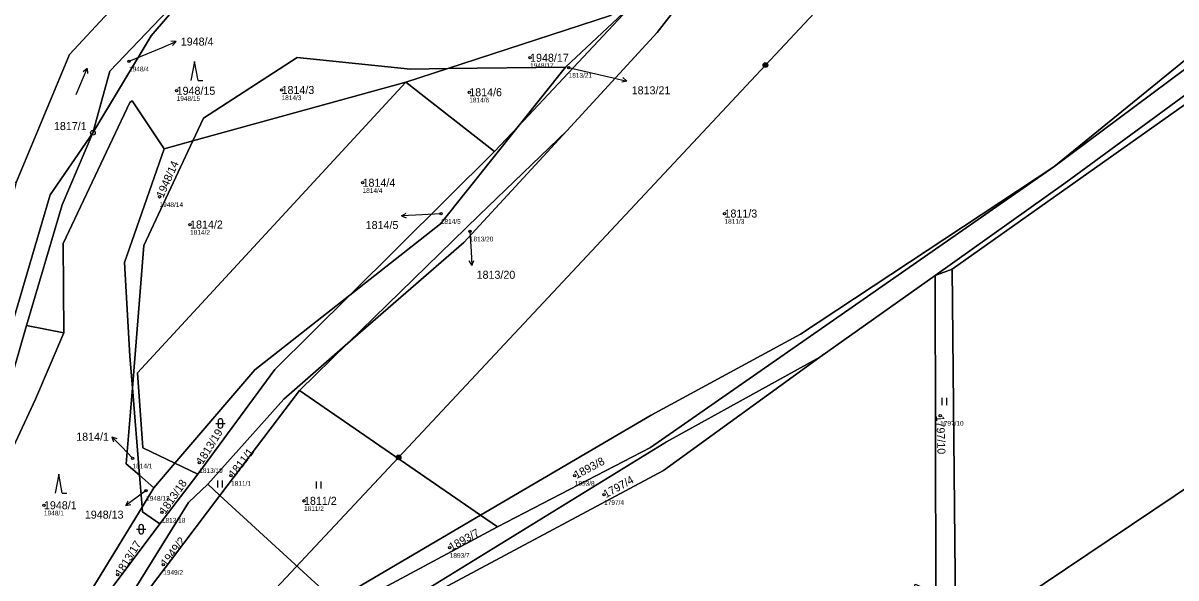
# Model space of a CAD drawing. Extents: x -762274 to -759271, y -1061928 to -1059060.
# Drawn here: x -761266.1 to -761021.1, y -1060846.7 to -1060728.9 of the extents above; entities that cross this region are included whole.
import ezdxf

# ---------------------------------------------------------------- set-up
doc = ezdxf.new("R2010")
doc.units = 0
for name, color, linetype in [('Definiční body', 7, 'Continuous'), ('Hranice parcel', 7, 'Continuous'), ('Parcelní čísla', 7, 'Continuous'), ('Polygon parcely', 7, 'Continuous'), ('Pop  PČ popisy', 7, 'Continuous'), ('Poz předměty', 7, 'Continuous'), ('Značky bodu BP', 7, 'Continuous'), ('Značky kultur', 7, 'Continuous')]:
    doc.layers.add(name, color=color, linetype=linetype)

msp = doc.modelspace()

# ---------------------------------------------------------------- linework, layer by layer
at = {"layer": 'Definiční body'}
for centre in [(-761243.55, -1060737), (-761158.36, -1060736.26), (-761150.17, -1060738.33), (-761233.45, -1060743.27), (-761211.16, -1060743.1), (-761171.28, -1060743.58), (-761193.95, -1060762.8), (-761237.08, -1060765.79), (-761177.31, -1060769.37), (-761117.05, -1060769.34), (-761230.59, -1060771.67), (-761171.15, -1060773.09), (-761071.23, -1060812.24), (-761242.82, -1060821.3), (-761228.64, -1060822.27), (-761221.88, -1060824.99), (-761148.87, -1060824.98), (-761239.93, -1060828.18), (-761142.63, -1060829.05), (-761261.64, -1060831.29), (-761206.39, -1060830.35), (-761236.58, -1060832.82), (-761175.43, -1060840.28), (-761236.3, -1060843.9), (-761245.95, -1060846.02)]:
    msp.add_circle(centre, 0.25, dxfattribs=at)
at = {"layer": 'Hranice parcel'}
for p, q in [((-761136.35, -1060724.75), (-761160.9, -1060750.86)), ((-761136.35, -1060724.75), (-761150.83, -1060738.27)), ((-761175.85, -1060738.56), (-761141.29, -1060727.28)), ((-761150.83, -1060738.27), (-761175.85, -1060738.56)), ((-761150.83, -1060738.27), (-761160.9, -1060750.86)), ((-761184.74, -1060741.46), (-761175.85, -1060738.56)), ((-761184.74, -1060741.46), (-761229.98, -1060753.9)), ((-761165.91, -1060756.19), (-761184.74, -1060741.46)), ((-761160.9, -1060750.86), (-761165.91, -1060756.19)), ((-761229.98, -1060753.9), (-761236.08, -1060755.58)), ((-761196.66, -1060786.66), (-761165.91, -1060756.19)), ((-761068.71, -1060781.12), (-761072.32, -1060782.49)), ((-761067.91, -1060860.48), (-761068.71, -1060781.12)), ((-761072.32, -1060782.49), (-761096.77, -1060799.85)), ((-761072.15, -1060849.9), (-761072.32, -1060782.49)), ((-761257.42, -1060794.67), (-761265.37, -1060793.08)), ((-761207.35, -1060806.93), (-761197.07, -1060796.9)), ((-761241.35, -1060824.93), (-761242.86, -1060806.32)), ((-761224.24, -1060829.21), (-761207.35, -1060806.93)), ((-761168.87, -1060833.39), (-761207.35, -1060806.93)), ((-761233.8, -1060822.36), (-761238.26, -1060827.57)), ((-761228.92, -1060824.71), (-761233.8, -1060822.36)), ((-761241.35, -1060824.93), (-761238.26, -1060827.57)), ((-761240.8, -1060831.72), (-761241.35, -1060824.93)), ((-761228.92, -1060824.71), (-761237.04, -1060835.2)), ((-761238.26, -1060827.57), (-761240.8, -1060831.72)), ((-761226.82, -1060826.84), (-761224.24, -1060829.21)), ((-761224.24, -1060829.21), (-761199.86, -1060851.57)), ((-761269.22, -1060878.2), (-761240.8, -1060831.72)), ((-761199.86, -1060851.57), (-761168.87, -1060833.39)), ((-761165.27, -1060835.87), (-761168.87, -1060833.39)), ((-761237.04, -1060835.2), (-761269.22, -1060878.2))]:
    msp.add_line(p, q, dxfattribs=at)
for points in [[(-761150.58, -1060751.74), (-761131.38, -1060730.87), (-761089.23, -1060676.77)], [(-760956.23, -1060685.96), (-760987.34, -1060716.59), (-761010.54, -1060737.84), (-761044.51, -1060762.75), (-761072.32, -1060782.49)], [(-761217.1, -1060693.41), (-761256.19, -1060735.55), (-761267.53, -1060762.74)], [(-761047.09, -1060759.39), (-761014.77, -1060733.14), (-760991.21, -1060712.56), (-760986.53, -1060707.75)], [(-760985.12, -1060709.16), (-761001.82, -1060725.75), (-761047.09, -1060759.39)], [(-761251.25, -1060752.17), (-761238.85, -1060731.63), (-761224.56, -1060714.9)], [(-761251.25, -1060752.17), (-761247.66, -1060739.1), (-761224.56, -1060714.9)], [(-760998.26, -1060731.71), (-761019.31, -1060746.24), (-761068.71, -1060781.12)], [(-761175.85, -1060738.56), (-761183.77, -1060738.65), (-761207.85, -1060736.23), (-761227.73, -1060749.1), (-761229.98, -1060753.9)], [(-761233.8, -1060822.36), (-761240.63, -1060819.07), (-761241.79, -1060803.18), (-761184.74, -1060741.46)], [(-761236.08, -1060755.58), (-761242.87, -1060745.4), (-761243.41, -1060745.74), (-761257.57, -1060775.67), (-761257.42, -1060794.67)], [(-761322.34, -1060894.54), (-761306.2, -1060874.72), (-761295.06, -1060858.65), (-761282.76, -1060836.42), (-761271.84, -1060804.34), (-761260.29, -1060765.39), (-761251.25, -1060752.17)], [(-761265.37, -1060793.08), (-761257.78, -1060767.49), (-761251.25, -1060752.17)], [(-761150.58, -1060751.74), (-761172.46, -1060775.52), (-761197.07, -1060796.9)], [(-761197.07, -1060796.9), (-761169.2, -1060769.68), (-761150.58, -1060751.74)], [(-761160.9, -1060750.86), (-761177.42, -1060771.52), (-761196.66, -1060786.66)], [(-761229.98, -1060753.9), (-761240.39, -1060776.11), (-761242.86, -1060806.32)], [(-761242.86, -1060806.32), (-761243.4, -1060799.63), (-761244.52, -1060779.75), (-761236.08, -1060755.58)], [(-761168.87, -1060833.39), (-761132.66, -1060812.15), (-761100.92, -1060794.93), (-761047.09, -1060759.39)], [(-761047.09, -1060759.39), (-761132.79, -1060819.05), (-761165.27, -1060835.87)], [(-760940.46, -1060777.01), (-760979.27, -1060801), (-761067.91, -1060860.48)], [(-761196.66, -1060786.66), (-761216.82, -1060802.53), (-761233.8, -1060822.36)], [(-761196.66, -1060786.66), (-761212.59, -1060802.45), (-761228.92, -1060824.71)], [(-761257.42, -1060794.67), (-761263.46, -1060808.77), (-761271.01, -1060824.88), (-761282.26, -1060861.39), (-761309.99, -1060889.4), (-761332.25, -1060918.32), (-761344.99, -1060927.62), (-761357.23, -1060933.34)], [(-761322.34, -1060894.54), (-761311.63, -1060884.88), (-761291.98, -1060860.89), (-761277.62, -1060835.42), (-761265.37, -1060793.08)], [(-761226.82, -1060826.84), (-761210.7, -1060808.73), (-761197.07, -1060796.9)], [(-761096.77, -1060799.85), (-761129.39, -1060817.83), (-761194.75, -1060858.03), (-761196.4, -1060859.25)], [(-761176.9, -1060848.97), (-761130.01, -1060823.92), (-761096.77, -1060799.85)], [(-761241.35, -1060824.93), (-761244.18, -1060822.51), (-761242.86, -1060806.32)], [(-761255.81, -1060870.74), (-761230.94, -1060830.68), (-761226.82, -1060826.84)], [(-761224.24, -1060829.21), (-761234.57, -1060842.83), (-761255.81, -1060870.74)], [(-761237.04, -1060835.2), (-761240.72, -1060832.67), (-761240.8, -1060831.72)], [(-761165.27, -1060835.87), (-761205.15, -1060857.25), (-761212.81, -1060861.91)]]:
    msp.add_lwpolyline(points, dxfattribs=at)
at = {"layer": 'Polygon parcely'}
for points in [[(-760986.1, -1060427.01), (-761021.62, -1060461.75), (-761022.5, -1060462.61), (-761040.97, -1060481.7), (-761053.88, -1060494.01), (-761069.92, -1060510.73), (-761079.43, -1060561.33), (-761089.56, -1060581.89), (-761099.86, -1060588.03), (-761128.14, -1060604.64), (-761140.02, -1060611.62), (-761149.18, -1060620.52), (-761153.48, -1060624.27), (-761155.89, -1060626.89), (-761214.07, -1060690.14), (-761217.1, -1060693.41), (-761256.19, -1060735.55), (-761267.53, -1060762.74), (-761275.36, -1060791.23), (-761278.82, -1060803.8), (-761288.4, -1060833.69), (-761301.74, -1060855.91), (-761311.33, -1060870.36), (-761329.82, -1060890.35)], [(-761271.84, -1060804.34), (-761260.29, -1060765.39), (-761251.25, -1060752.17), (-761247.66, -1060739.1), (-761224.56, -1060714.9), (-761213.5, -1060703.49), (-761207.85, -1060697.66), (-761147.16, -1060632.45), (-761145.06, -1060630.19), (-761131.3, -1060618.58), (-761095.24, -1060593.07), (-761084.28, -1060581.28), (-761075.53, -1060563.54), (-761068.42, -1060523.86), (-761062.44, -1060514.01), (-761052.71, -1060501.89), (-761037.42, -1060487.37), (-761035.26, -1060484.89), (-761025.32, -1060476.46), (-761017.38, -1060469.64)], [(-761269.22, -1060878.2), (-761240.8, -1060831.72), (-761241.35, -1060824.93), (-761244.18, -1060822.51), (-761242.86, -1060806.32), (-761243.4, -1060799.63), (-761244.52, -1060779.75), (-761236.08, -1060755.58), (-761242.87, -1060745.4), (-761243.41, -1060745.74), (-761257.57, -1060775.67), (-761257.42, -1060794.67), (-761263.46, -1060808.77), (-761271.01, -1060824.88)]]:
    msp.add_lwpolyline(points, dxfattribs=at)
for points in [[(-761010.54, -1060737.84), (-761044.51, -1060762.75), (-761072.32, -1060782.49), (-761068.71, -1060781.12), (-761019.31, -1060746.24), (-760998.26, -1060731.71), (-760977.63, -1060710.74), (-760951.25, -1060688.71), (-760936.2, -1060676.76), (-760933.83, -1060674.97), (-760921.43, -1060661.84), (-760891.41, -1060629.81), (-760884.45, -1060617.18), (-760890.91, -1060624.68), (-760920.97, -1060652.28), (-760926.73, -1060658.56), (-760939.63, -1060672.64), (-760956.23, -1060685.96), (-760987.34, -1060716.59)], [(-761261.47, -1060634.17), (-761268.62, -1060626.09), (-761333.35, -1060711.53), (-761364.51, -1060749.36), (-761306.96, -1060796.48), (-761300.33, -1060786.52), (-761290.49, -1060780.8), (-761275.58, -1060760.1), (-761267.53, -1060762.74), (-761256.19, -1060735.55), (-761217.1, -1060693.41), (-761221.44, -1060691.82), (-761240.65, -1060679.96), (-761229.58, -1060659.37), (-761237.29, -1060653.65), (-761241.79, -1060652.49)], [(-761089.23, -1060676.77), (-761131.38, -1060730.87), (-761150.58, -1060751.74), (-761172.46, -1060775.52), (-761197.07, -1060796.9), (-761207.35, -1060806.93), (-761168.87, -1060833.39), (-761132.66, -1060812.15), (-761100.92, -1060794.93), (-761047.09, -1060759.39), (-761014.77, -1060733.14), (-760991.21, -1060712.56), (-760986.53, -1060707.75), (-761055.77, -1060638.88)], [(-761141.29, -1060727.28), (-761143.4, -1060662), (-761146.9, -1060677.31), (-761151.84, -1060691.43), (-761165.92, -1060714.26), (-761176, -1060722.65), (-761193.74, -1060720.96), (-761198.85, -1060715.54), (-761224.56, -1060714.9), (-761238.85, -1060731.63), (-761251.25, -1060752.17), (-761257.78, -1060767.49), (-761265.37, -1060793.08), (-761257.42, -1060794.67), (-761257.57, -1060775.67), (-761243.41, -1060745.74), (-761242.87, -1060745.4), (-761236.08, -1060755.58), (-761229.98, -1060753.9), (-761227.73, -1060749.1), (-761207.85, -1060736.23), (-761183.77, -1060738.65), (-761175.85, -1060738.56)], [(-761136.35, -1060724.75), (-761160.9, -1060750.86), (-761177.42, -1060771.52), (-761196.66, -1060786.66), (-761212.59, -1060802.45), (-761228.92, -1060824.71), (-761237.04, -1060835.2), (-761269.22, -1060878.2), (-761298.8, -1060926.56), (-761348.67, -1060986.94), (-761354.62, -1061001.46), (-761299.71, -1060929.29), (-761269.45, -1060888.66), (-761255.81, -1060870.74), (-761230.94, -1060830.68), (-761226.82, -1060826.84), (-761210.7, -1060808.73), (-761197.07, -1060796.9), (-761169.2, -1060769.68), (-761150.58, -1060751.74), (-761131.38, -1060730.87), (-761089.23, -1060676.77), (-761095.67, -1060673.39)], [(-761132.79, -1060819.05), (-761165.27, -1060835.87), (-761205.15, -1060857.25), (-761212.81, -1060861.91), (-761211.5, -1060867.36), (-761207.78, -1060865.29), (-761204.41, -1060863.47), (-761196.4, -1060859.25), (-761194.75, -1060858.03), (-761129.39, -1060817.83), (-761096.77, -1060799.85), (-761072.32, -1060782.49), (-761044.51, -1060762.75), (-761010.54, -1060737.84), (-760987.34, -1060716.59), (-760956.23, -1060685.96), (-760985.12, -1060709.16), (-761001.82, -1060725.75), (-761047.09, -1060759.39)], [(-760985.12, -1060709.16), (-760986.53, -1060707.75), (-760991.21, -1060712.56), (-761014.77, -1060733.14), (-761047.09, -1060759.39), (-761001.82, -1060725.75)], [(-761238.85, -1060731.63), (-761224.56, -1060714.9), (-761247.66, -1060739.1), (-761251.25, -1060752.17)], [(-761136.35, -1060724.75), (-761141.29, -1060727.28), (-761175.85, -1060738.56), (-761150.83, -1060738.27)], [(-761150.83, -1060738.27), (-761160.9, -1060750.86), (-761136.35, -1060724.75)], [(-760940.46, -1060777.01), (-760998.26, -1060731.71), (-761019.31, -1060746.24), (-761068.71, -1060781.12), (-761067.91, -1060860.48), (-760979.27, -1060801)], [(-761227.73, -1060749.1), (-761229.98, -1060753.9), (-761184.74, -1060741.46), (-761175.85, -1060738.56), (-761183.77, -1060738.65), (-761207.85, -1060736.23)], [(-761150.83, -1060738.27), (-761175.85, -1060738.56), (-761184.74, -1060741.46), (-761165.91, -1060756.19), (-761160.9, -1060750.86)], [(-761241.79, -1060803.18), (-761184.74, -1060741.46), (-761229.98, -1060753.9), (-761240.39, -1060776.11), (-761242.86, -1060806.32), (-761241.35, -1060824.93), (-761238.26, -1060827.57), (-761233.8, -1060822.36), (-761240.63, -1060819.07)], [(-761165.91, -1060756.19), (-761184.74, -1060741.46), (-761241.79, -1060803.18), (-761240.63, -1060819.07), (-761233.8, -1060822.36), (-761216.82, -1060802.53), (-761196.66, -1060786.66)], [(-761257.78, -1060767.49), (-761251.25, -1060752.17), (-761260.29, -1060765.39), (-761271.84, -1060804.34), (-761282.76, -1060836.42), (-761295.06, -1060858.65), (-761306.2, -1060874.72), (-761322.34, -1060894.54), (-761311.63, -1060884.88), (-761291.98, -1060860.89), (-761277.62, -1060835.42), (-761265.37, -1060793.08)], [(-761150.58, -1060751.74), (-761169.2, -1060769.68), (-761197.07, -1060796.9), (-761172.46, -1060775.52)], [(-761160.9, -1060750.86), (-761165.91, -1060756.19), (-761196.66, -1060786.66), (-761177.42, -1060771.52)], [(-761229.98, -1060753.9), (-761236.08, -1060755.58), (-761244.52, -1060779.75), (-761243.4, -1060799.63), (-761242.86, -1060806.32), (-761240.39, -1060776.11)], [(-761047.09, -1060759.39), (-761100.92, -1060794.93), (-761132.66, -1060812.15), (-761168.87, -1060833.39), (-761165.27, -1060835.87), (-761132.79, -1060819.05)], [(-760979.27, -1060801), (-761067.91, -1060860.48), (-761067.76, -1060874.87), (-761070.55, -1060880.49), (-761065.03, -1060879.35), (-761054.68, -1060874.04), (-761054.39, -1060873.88), (-761018.18, -1060853.45), (-761005.24, -1060848.61), (-760993.33, -1060844.12), (-760977.26, -1060835.18), (-760965.88, -1060828.86), (-760950.08, -1060803.55), (-760928.26, -1060786.58), (-760940.46, -1060777.01)], [(-761068.71, -1060781.12), (-761072.32, -1060782.49), (-761072.15, -1060849.9), (-761069.15, -1060851.14), (-761068.54, -1060860.9), (-761067.91, -1060860.48)], [(-761072.15, -1060849.9), (-761072.32, -1060782.49), (-761096.77, -1060799.85), (-761130.01, -1060823.92), (-761176.9, -1060848.97), (-761159.24, -1060874.27), (-761139.04, -1060904.51), (-761133.78, -1060914.3), (-761126.74, -1060910.72), (-761120.57, -1060907.59), (-761121.2, -1060900.1), (-761080.53, -1060865.95), (-761076.54, -1060848.08)], [(-761216.82, -1060802.53), (-761233.8, -1060822.36), (-761228.92, -1060824.71), (-761212.59, -1060802.45), (-761196.66, -1060786.66)], [(-761257.42, -1060794.67), (-761265.37, -1060793.08), (-761277.62, -1060835.42), (-761291.98, -1060860.89), (-761311.63, -1060884.88), (-761322.34, -1060894.54), (-761344.13, -1060913), (-761362.69, -1060923.99), (-761377.15, -1060926.04), (-761366.55, -1060930.2), (-761357.23, -1060933.34), (-761344.99, -1060927.62), (-761332.25, -1060918.32), (-761309.99, -1060889.4), (-761282.26, -1060861.39), (-761271.01, -1060824.88), (-761263.46, -1060808.77)], [(-761207.35, -1060806.93), (-761197.07, -1060796.9), (-761210.7, -1060808.73), (-761226.82, -1060826.84), (-761224.24, -1060829.21)], [(-761129.39, -1060817.83), (-761194.75, -1060858.03), (-761196.4, -1060859.25), (-761176.9, -1060848.97), (-761130.01, -1060823.92), (-761096.77, -1060799.85)], [(-761241.35, -1060824.93), (-761242.86, -1060806.32), (-761244.18, -1060822.51)], [(-761168.87, -1060833.39), (-761207.35, -1060806.93), (-761224.24, -1060829.21), (-761199.86, -1060851.57)], [(-761233.8, -1060822.36), (-761238.26, -1060827.57), (-761240.8, -1060831.72), (-761240.72, -1060832.67), (-761237.04, -1060835.2), (-761228.92, -1060824.71)], [(-761241.35, -1060824.93), (-761240.8, -1060831.72), (-761238.26, -1060827.57)], [(-761226.82, -1060826.84), (-761230.94, -1060830.68), (-761255.81, -1060870.74), (-761234.57, -1060842.83), (-761224.24, -1060829.21)], [(-761234.57, -1060842.83), (-761255.81, -1060870.74), (-761292.12, -1060929.22), (-761246.24, -1060940.46), (-761251.15, -1060895.57), (-761245.93, -1060883.42), (-761237.28, -1060873.67), (-761213.19, -1060860.3), (-761199.86, -1060851.57), (-761224.24, -1060829.21)], [(-761240.72, -1060832.67), (-761240.8, -1060831.72), (-761269.22, -1060878.2), (-761237.04, -1060835.2)], [(-761213.19, -1060860.3), (-761212.81, -1060861.91), (-761205.15, -1060857.25), (-761165.27, -1060835.87), (-761168.87, -1060833.39), (-761199.86, -1060851.57)]]:
    msp.add_lwpolyline(points, close=True, dxfattribs=at)
at = {"layer": 'Pop  PČ popisy'}
for p, q in [((-761236.34, -1060733.98), (-761233.58, -1060732.81)), ((-761233.58, -1060732.81), (-761234.7, -1060732.74)), ((-761233.58, -1060732.81), (-761234.3, -1060733.66)), ((-761243.55, -1060737), (-761236.34, -1060733.98)), ((-761150.17, -1060738.33), (-761140.69, -1060740.52)), ((-761140.69, -1060740.52), (-761137.77, -1060741.2)), ((-761137.77, -1060741.2), (-761138.63, -1060740.48)), ((-761137.77, -1060741.2), (-761138.85, -1060741.46)), ((-761185.68, -1060769.81), (-761184.7, -1060769.26)), ((-761182.68, -1060769.65), (-761185.68, -1060769.81)), ((-761185.68, -1060769.81), (-761184.65, -1060770.26)), ((-761177.31, -1060769.37), (-761182.68, -1060769.65)), ((-761171.15, -1060773.09), (-761170.9, -1060777.37)), ((-761170.9, -1060777.37), (-761170.74, -1060780.37)), ((-761170.74, -1060780.37), (-761171.3, -1060779.39)), ((-761170.74, -1060780.37), (-761170.3, -1060779.34)), ((-761245.1, -1060818.9), (-761247.19, -1060816.74)), ((-761247.19, -1060816.74), (-761246.13, -1060817.11)), ((-761247.19, -1060816.74), (-761246.85, -1060817.81)), ((-761242.82, -1060821.3), (-761245.1, -1060818.9)), ((-761239.93, -1060828.18), (-761241.83, -1060829.55)), ((-761241.83, -1060829.55), (-761244.26, -1060831.31)), ((-761244.26, -1060831.31), (-761243.74, -1060830.32)), ((-761244.26, -1060831.31), (-761243.15, -1060831.13))]:
    msp.add_line(p, q, dxfattribs=at)
at = {"layer": 'Poz předměty'}
for p, q in [((-761047.07, -1060672.52), (-761108.37, -1060737.82)), ((-761108.37, -1060737.82), (-761186.3, -1060821.12)), ((-761186.3, -1060821.12), (-761264.58, -1060904.64))]:
    msp.add_line(p, q, dxfattribs=at)
for centre, radius in [((-761108.37, -1060737.82), 0.5), ((-761108.37, -1060737.82), 0.4), ((-761108.37, -1060737.82), 0.3), ((-761108.37, -1060737.82), 0.2), ((-761108.37, -1060737.82), 0.1), ((-761186.3, -1060821.12), 0.5), ((-761186.3, -1060821.12), 0.4), ((-761186.3, -1060821.12), 0.3), ((-761186.3, -1060821.12), 0.2), ((-761186.3, -1060821.12), 0.1)]:
    msp.add_circle(centre, radius, dxfattribs=at)
at = {"layer": 'Značky bodu BP'}
for radius in [0.5, 0.0303]:
    msp.add_circle((-761251.25, -1060752.17), radius, dxfattribs=at)
at = {"layer": 'Značky kultur'}
for p, q in [((-761229.66, -1060737.07), (-761230.41, -1060741.07)), ((-761228.91, -1060741.07), (-761229.66, -1060737.07)), ((-761254.79, -1060744.05), (-761252.44, -1060738.53)), ((-761252.44, -1060738.53), (-761253.29, -1060739.23)), ((-761252.44, -1060738.53), (-761252.36, -1060739.62)), ((-761228.91, -1060741.07), (-761227.91, -1060741.07)), ((-761070.79, -1060810.01), (-761070.79, -1060808.51)), ((-761069.79, -1060810.01), (-761069.79, -1060808.51)), ((-761225.15, -1060813.92), (-761223.15, -1060813.92)), ((-761224.65, -1060813.42), (-761224.65, -1060814.42)), ((-761223.65, -1060814.42), (-761223.65, -1060813.42)), ((-761258.5, -1060824.7), (-761259.25, -1060828.7)), ((-761257.75, -1060828.7), (-761258.5, -1060824.7)), ((-761224.69, -1060827.55), (-761224.69, -1060826.05)), ((-761223.69, -1060827.55), (-761223.69, -1060826.05)), ((-761203.71, -1060827.71), (-761203.71, -1060826.21)), ((-761202.71, -1060827.71), (-761202.71, -1060826.21)), ((-761257.75, -1060828.7), (-761256.75, -1060828.7)), ((-761241.47, -1060835.89), (-761241.47, -1060836.89)), ((-761240.47, -1060836.89), (-761240.47, -1060835.89)), ((-761241.97, -1060836.39), (-761239.97, -1060836.39))]:
    msp.add_line(p, q, dxfattribs=at)
for centre, start, end in [((-761224.15, -1060813.42), 0, 180), ((-761224.15, -1060814.42), 180, 359.9879), ((-761240.97, -1060835.89), 0, 180), ((-761240.97, -1060836.89), 180, 359.9879)]:
    msp.add_arc(centre, 0.5, start, end, dxfattribs=at)

# ---------------------------------------------------------------- texts
at = {"layer": 'Definiční body'}
for s, p in [('1948/4', (-761243.55, -1060739.16)), ('1948/17', (-761158.36, -1060738.42)), ('1813/21', (-761150.17, -1060740.49)), ('1948/15', (-761233.45, -1060745.43)), ('1814/3', (-761211.16, -1060745.26)), ('1814/6', (-761171.28, -1060745.74)), ('1814/4', (-761193.95, -1060764.96)), ('1948/14', (-761237.08, -1060767.95)), ('1814/5', (-761177.31, -1060771.53)), ('1811/3', (-761117.05, -1060771.5)), ('1814/2', (-761230.59, -1060773.83)), ('1813/20', (-761171.15, -1060775.25)), ('1797/10', (-761071.23, -1060814.4)), ('1814/1', (-761242.82, -1060823.46)), ('1813/19', (-761228.64, -1060824.43)), ('1811/1', (-761221.88, -1060827.15)), ('1893/8', (-761148.87, -1060827.14)), ('1948/13', (-761239.93, -1060830.34)), ('1797/4', (-761142.63, -1060831.21)), ('1948/1', (-761261.64, -1060833.45)), ('1811/2', (-761206.39, -1060832.51)), ('1813/18', (-761236.58, -1060834.98)), ('1893/7', (-761175.43, -1060842.44)), ('1949/2', (-761236.3, -1060846.06))]:
    msp.add_text(s, height=1, dxfattribs=at).set_placement(p)
at = {"layer": 'Parcelní čísla'}
for s, p in [('1948/4', (-761232.57, -1060733.67)), ('1948/17', (-761158.36, -1060737.11)), ('1948/15', (-761233.45, -1060744.12)), ('1814/3', (-761211.16, -1060743.95)), ('1814/6', (-761171.28, -1060744.43)), ('1813/21', (-761136.77, -1060744.02)), ('1817/1', (-761259.52, -1060751.61)), ('1814/4', (-761193.95, -1060763.65)), ('1811/3', (-761117.05, -1060770.19)), ('1814/2', (-761230.59, -1060772.52)), ('1814/5', (-761193.29, -1060772.63)), ('1813/20', (-761169.72, -1060783.19)), ('1814/1', (-761254.78, -1060817.58)), ('1948/1', (-761261.64, -1060832.14)), ('1811/2', (-761206.39, -1060831.2)), ('1948/13', (-761252.95, -1060834.13))]:
    msp.add_text(s, height=1.7, dxfattribs=at).set_placement(p)
for s, rotation, p in [('1948/14', 66, (-761236.3, -1060766.14)), ('1797/10', 272, (-761072.08, -1060812.27)), ('1813/19', 58, (-761227.92, -1060822.72)), ('1811/1', 52, (-761221.21, -1060825.51)), ('1893/8', 28, (-761148.47, -1060825.73)), ('1813/18', 55, (-761235.88, -1060833.31)), ('1797/4', 29, (-761142.22, -1060829.79)), ('1893/7', 29, (-761175.02, -1060841.02)), ('1813/17', 58, (-761245.23, -1060846.47)), ('1949/2', 53, (-761235.62, -1060844.41))]:
    msp.add_text(s, height=1.7, rotation=rotation, dxfattribs=at).set_placement(p)

doc.saveas('drawing.dxf')
